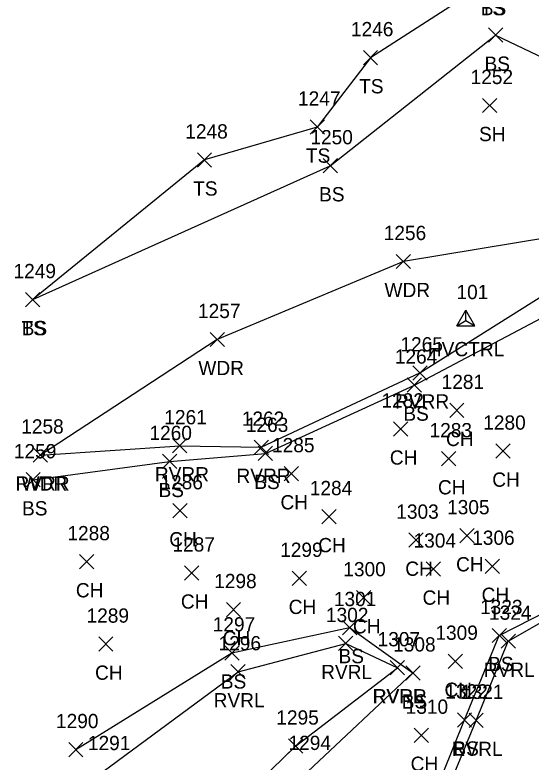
# Model space of a CAD drawing. Extents: x 1678553 to 1680768, y 787260 to 792325.
# Drawn here: x 1678583.5 to 1678655.8, y 787483.5 to 787588.2 of the extents above; entities that cross this region are included whole.
import ezdxf

# ---------------------------------------------------------------- set-up
doc = ezdxf.new("R2010")
doc.units = 0
for name, color, linetype in [('C_A', 7, 'Continuous'), ('C_I', 7, 'Continuous'), ('CPSM', 7, 'Continuous'), ('L_A', 7, 'Continuous'), ('L_I', 7, 'Continuous'), ('L_TIC', 7, 'Continuous'), ('LAWA', 7, 'Continuous'), ('LAWE', 7, 'Continuous'), ('LELB', 7, 'Continuous')]:
    doc.layers.add(name, color=color, linetype=linetype)

msp = doc.modelspace()

# ---------------------------------------------------------------- linework, layer by layer
at = {"layer": 'CPSM'}
for p, q in [((1678645.4, 787544.69), (1678646.65, 787546.85)), ((1678647.9, 787544.69), (1678646.65, 787546.85)), ((1678646.65, 787545.41), (1678646.65, 787546.85)), ((1678645.4, 787544.69), (1678646.65, 787545.41)), ((1678645.4, 787544.69), (1678647.9, 787544.69)), ((1678646.65, 787545.41), (1678646.65, 787545.41)), ((1678646.65, 787545.41), (1678647.9, 787544.69))]:
    msp.add_line(p, q, dxfattribs=at)
at = {"layer": 'L_TIC'}
for points in [[(1678649.83, 787584.41), (1678651.83, 787586.41)], [(1678651.83, 787584.41), (1678649.83, 787586.41)], [(1678632.3, 787581.25), (1678634.3, 787583.25)], [(1678634.3, 787581.25), (1678632.3, 787583.25)], [(1678649.01, 787574.55), (1678651.01, 787576.55)], [(1678651.01, 787574.55), (1678649.01, 787576.55)], [(1678624.84, 787571.53), (1678626.84, 787573.53)], [(1678626.84, 787571.53), (1678624.84, 787573.53)], [(1678609.05, 787566.92), (1678611.05, 787568.92)], [(1678611.05, 787566.92), (1678609.05, 787568.92)], [(1678626.66, 787566.11), (1678628.66, 787568.11)], [(1678628.66, 787566.11), (1678626.66, 787568.11)], [(1678636.9, 787552.69), (1678638.9, 787554.69)], [(1678638.9, 787552.69), (1678636.9, 787554.69)], [(1678585, 787547.35), (1678587, 787549.35)], [(1678587, 787547.35), (1678585, 787549.35)], [(1678585, 787547.35), (1678587, 787549.35)], [(1678587, 787547.35), (1678585, 787549.35)], [(1678610.83, 787541.76), (1678612.83, 787543.76)], [(1678612.83, 787541.76), (1678610.83, 787543.76)], [(1678639.23, 787537.08), (1678641.23, 787539.08)], [(1678641.23, 787537.08), (1678639.23, 787539.08)], [(1678638.45, 787535.37), (1678640.45, 787537.37)], [(1678640.45, 787535.37), (1678638.45, 787537.37)], [(1678644.39, 787531.82), (1678646.39, 787533.82)], [(1678646.39, 787531.82), (1678644.39, 787533.82)], [(1678636.52, 787529.22), (1678638.52, 787531.22)], [(1678638.52, 787529.22), (1678636.52, 787531.22)], [(1678605.59, 787526.87), (1678607.59, 787528.87)], [(1678607.59, 787526.87), (1678605.59, 787528.87)], [(1678617.01, 787526.66), (1678619.01, 787528.66)], [(1678619.01, 787526.66), (1678617.01, 787528.66)], [(1678650.87, 787526.12), (1678652.87, 787528.12)], [(1678652.87, 787526.12), (1678650.87, 787528.12)], [(1678586.07, 787525.57), (1678588.07, 787527.57)], [(1678588.07, 787525.57), (1678586.07, 787527.57)], [(1678586.07, 787525.57), (1678588.07, 787527.57)], [(1678588.07, 787525.57), (1678586.07, 787527.57)], [(1678617.58, 787525.8), (1678619.58, 787527.8)], [(1678619.58, 787525.8), (1678617.58, 787527.8)], [(1678643.26, 787525.05), (1678645.26, 787527.05)], [(1678645.26, 787525.05), (1678643.26, 787527.05)], [(1678604.17, 787524.67), (1678606.17, 787526.67)], [(1678606.17, 787524.67), (1678604.17, 787526.67)], [(1678621.21, 787522.95), (1678623.21, 787524.95)], [(1678623.21, 787522.95), (1678621.21, 787524.95)], [(1678585.05, 787522.1), (1678587.05, 787524.1)], [(1678587.05, 787522.1), (1678585.05, 787524.1)], [(1678605.63, 787517.76), (1678607.63, 787519.76)], [(1678607.63, 787517.76), (1678605.63, 787519.76)], [(1678626.49, 787516.94), (1678628.49, 787518.94)], [(1678628.49, 787516.94), (1678626.49, 787518.94)], [(1678638.68, 787513.64), (1678640.68, 787515.64)], [(1678640.68, 787513.64), (1678638.68, 787515.64)], [(1678645.8, 787514.26), (1678647.8, 787516.26)], [(1678647.8, 787514.26), (1678645.8, 787516.26)], [(1678592.54, 787510.62), (1678594.54, 787512.62)], [(1678594.54, 787510.62), (1678592.54, 787512.62)], [(1678641.1, 787509.59), (1678643.1, 787511.59)], [(1678643.1, 787509.59), (1678641.1, 787511.59)], [(1678649.37, 787509.98), (1678651.37, 787511.98)], [(1678651.37, 787509.98), (1678649.37, 787511.98)], [(1678607.26, 787509.04), (1678609.26, 787511.04)], [(1678609.26, 787509.04), (1678607.26, 787511.04)], [(1678622.35, 787508.29), (1678624.35, 787510.29)], [(1678624.35, 787508.29), (1678622.35, 787510.29)], [(1678631.35, 787505.57), (1678633.35, 787507.57)], [(1678633.35, 787505.57), (1678631.35, 787507.57)], [(1678613.11, 787503.91), (1678615.11, 787505.91)], [(1678615.11, 787503.91), (1678613.11, 787505.91)], [(1678629.37, 787501.39), (1678631.37, 787503.39)], [(1678631.37, 787501.39), (1678629.37, 787503.39)], [(1678650.34, 787500.28), (1678652.34, 787502.28)], [(1678652.34, 787500.28), (1678650.34, 787502.28)], [(1678595.23, 787499.07), (1678597.23, 787501.07)], [(1678597.23, 787499.07), (1678595.23, 787501.07)], [(1678628.83, 787499.16), (1678630.83, 787501.16)], [(1678630.83, 787499.16), (1678628.83, 787501.16)], [(1678651.59, 787499.48), (1678653.59, 787501.48)], [(1678653.59, 787499.48), (1678651.59, 787501.48)], [(1678612.89, 787497.84), (1678614.89, 787499.84)], [(1678614.89, 787497.84), (1678612.89, 787499.84)], [(1678644.17, 787496.67), (1678646.17, 787498.67)], [(1678646.17, 787496.67), (1678644.17, 787498.67)], [(1678636.07, 787495.76), (1678638.07, 787497.76)], [(1678638.07, 787495.76), (1678636.07, 787497.76)], [(1678636.07, 787495.76), (1678638.07, 787497.76)], [(1678638.07, 787495.76), (1678636.07, 787497.76)], [(1678613.76, 787495.2), (1678615.76, 787497.2)], [(1678615.76, 787495.2), (1678613.76, 787497.2)], [(1678638.24, 787495.03), (1678640.24, 787497.03)], [(1678640.24, 787495.03), (1678638.24, 787497.03)], [(1678638.24, 787495.03), (1678640.24, 787497.03)], [(1678640.24, 787495.03), (1678638.24, 787497.03)], [(1678645.47, 787488.44), (1678647.47, 787490.44)], [(1678647.47, 787488.44), (1678645.47, 787490.44)], [(1678647.1, 787488.38), (1678649.1, 787490.38)], [(1678649.1, 787488.38), (1678647.1, 787490.38)], [(1678639.43, 787486.3), (1678641.43, 787488.3)], [(1678641.43, 787486.3), (1678639.43, 787488.3)], [(1678591.03, 787484.29), (1678593.03, 787486.29)], [(1678593.03, 787484.29), (1678591.03, 787486.29)], [(1678621.8, 787484.79), (1678623.8, 787486.79)], [(1678623.8, 787484.79), (1678621.8, 787486.79)]]:
    msp.add_lwpolyline(points, dxfattribs=at)
at = {"layer": 'LAWA'}
msp.add_lwpolyline([(1678599.45, 787627.07), (1678621.63, 787630.48), (1678629.13, 787625.9), (1678659.68, 787623.11), (1678672.05, 787619.87), (1678670.06, 787610.94), (1678664.34, 787597.34), (1678663.82, 787591.2), (1678674.57, 787583.12), (1678678.14, 787577.87), (1678672.71, 787567.7), (1678658.82, 787557.15), (1678637.9, 787553.69), (1678611.83, 787542.76), (1678587.07, 787526.57)], dxfattribs=at)
at = {"layer": 'LAWE'}
for points in [[(1678587.07, 787526.57), (1678606.59, 787527.87), (1678618.01, 787527.66), (1678640.23, 787538.08), (1678659.07, 787549.93), (1678671.7, 787548.98), (1678686.58, 787560.22)], [(1678597.83, 787442.87), (1678614, 787449.69), (1678631.37, 787455.12), (1678641.6, 787473.63), (1678648.1, 787489.38), (1678652.59, 787500.48), (1678670.34, 787510.61)], [(1678595.85, 787482.21), (1678614.76, 787496.2), (1678629.83, 787500.16), (1678637.07, 787496.76)], [(1678597.76, 787461.45), (1678622.8, 787485.79), (1678637.07, 787496.76)]]:
    msp.add_lwpolyline(points, dxfattribs=at)
at = {"layer": 'LELB'}
for points in [[(1678650.31, 787593.2), (1678633.3, 787582.25), (1678625.84, 787572.53), (1678610.05, 787567.92), (1678586, 787548.35)], [(1678586, 787548.35), (1678627.66, 787567.11), (1678650.83, 787585.41), (1678664.45, 787578.91), (1678672.71, 787567.7)], [(1678586.05, 787523.1), (1678605.17, 787525.67), (1678618.58, 787526.8), (1678639.45, 787536.37), (1678659.67, 787547.06), (1678672.48, 787547.1), (1678689.05, 787558.27)], [(1678597.93, 787443.89), (1678613.14, 787451.8), (1678631.31, 787457.63), (1678640.51, 787474.59), (1678646.47, 787489.44), (1678651.34, 787501.28), (1678669.62, 787510.64)], [(1678592.03, 787485.29), (1678613.89, 787498.84), (1678630.37, 787502.39), (1678639.24, 787496.03)], [(1678598.77, 787460.97), (1678624.52, 787482.23), (1678639.24, 787496.03)]]:
    msp.add_lwpolyline(points, dxfattribs=at)

# ---------------------------------------------------------------- texts
at = {"layer": 'C_A'}
msp.add_text('HVCTRL', height=2, dxfattribs=at).set_placement((1678641.34, 787540.41))
at = {"layer": 'C_I'}
msp.add_text('101', height=2, dxfattribs=at).set_placement((1678645.34, 787548.41))
at = {"layer": 'L_A'}
for s, p in [('TS', (1678648.72, 787588.2)), ('BS', (1678648.75, 787588.2)), ('BS', (1678649.27, 787580.41)), ('TS', (1678631.71, 787577.25)), ('SH', (1678648.5, 787570.55)), ('TS', (1678624.25, 787567.53)), ('TS', (1678608.46, 787562.92)), ('BS', (1678626.1, 787562.11)), ('WDR', (1678635.26, 787548.69)), ('TS', (1678584.41, 787543.35)), ('BS', (1678584.44, 787543.35)), ('WDR', (1678609.19, 787537.76)), ('RVRR', (1678636.74, 787533.08)), ('BS', (1678637.9, 787531.37)), ('CH', (1678643.88, 787527.82)), ('CH', (1678636.01, 787525.22)), ('RVRR', (1678603.1, 787522.87)), ('RVRR', (1678614.53, 787522.66)), ('BS', (1678617.02, 787521.8)), ('CH', (1678650.35, 787522.12)), ('RVRR', (1678583.58, 787521.57)), ('WDR', (1678584.43, 787521.57)), ('BS', (1678603.61, 787520.67)), ('CH', (1678642.75, 787521.05)), ('CH', (1678620.69, 787518.95)), ('BS', (1678584.49, 787518.1)), ('CH', (1678605.11, 787513.76)), ('CH', (1678625.98, 787512.94)), ('CH', (1678645.29, 787510.26)), ('CH', (1678638.17, 787509.64)), ('CH', (1678592.03, 787506.62)), ('CH', (1678648.86, 787505.98)), ('CH', (1678606.74, 787505.04)), ('CH', (1678640.59, 787505.59)), ('CH', (1678621.84, 787504.29)), ('CH', (1678630.84, 787501.57)), ('CH', (1678612.6, 787499.91)), ('BS', (1678628.82, 787497.39)), ('RVRL', (1678649.16, 787495.48)), ('BS', (1678649.78, 787496.28)), ('CH', (1678594.72, 787495.07)), ('RVRL', (1678626.39, 787495.16)), ('BS', (1678612.33, 787493.84)), ('CH', (1678643.66, 787492.67)), ('RVRR', (1678633.59, 787491.76)), ('RVRL', (1678633.64, 787491.76)), ('RVRL', (1678611.33, 787491.2)), ('BS', (1678637.68, 787491.03)), ('BS', (1678637.68, 787491.03)), ('RVRL', (1678644.67, 787484.38)), ('BS', (1678644.91, 787484.44)), ('CH', (1678638.92, 787482.3))]:
    msp.add_text(s, height=2, dxfattribs=at).set_placement(p)
at = {"layer": 'L_I'}
for s, p in [('1246', (1678630.56, 787585.25)), ('1252', (1678647.32, 787578.55)), ('1247', (1678623.15, 787575.53)), ('1248', (1678607.36, 787570.92)), ('1250', (1678624.88, 787570.11)), ('1256', (1678635.15, 787556.69)), ('1249', (1678583.3, 787551.35)), ('1249', (1678583.3, 787551.35)), ('1257', (1678609.14, 787545.76)), ('1265', (1678637.49, 787541.08)), ('1264', (1678636.71, 787539.37)), ('1281', (1678643.26, 787535.82)), ('1282', (1678634.83, 787533.22)), ('1261', (1678604.42, 787530.87)), ('1262', (1678615.27, 787530.66)), ('1280', (1678649.09, 787530.12)), ('1258', (1678584.38, 787529.57)), ('1258', (1678584.38, 787529.57)), ('1263', (1678615.84, 787529.8)), ('1283', (1678641.57, 787529.05)), ('1260', (1678602.34, 787528.67)), ('1285', (1678619.51, 787526.95)), ('1259', (1678583.35, 787526.1)), ('1286', (1678603.88, 787521.76)), ('1284', (1678624.8, 787520.94)), ('1303', (1678636.91, 787517.64)), ('1305', (1678644.03, 787518.26)), ('1288', (1678590.85, 787514.62)), ('1304', (1678639.33, 787513.59)), ('1306', (1678647.54, 787513.98)), ('1287', (1678605.56, 787513.04)), ('1299', (1678620.65, 787512.29)), ('1300', (1678629.49, 787509.57)), ('1298', (1678611.41, 787507.91)), ('1301', (1678628.17, 787505.39)), ('1323', (1678648.65, 787504.28)), ('1289', (1678593.53, 787503.07)), ('1302', (1678627.06, 787503.16)), ('1324', (1678649.9, 787503.48)), ('1297', (1678611.2, 787501.84)), ('1309', (1678642.39, 787500.67)), ('1307', (1678634.3, 787499.76)), ('1307', (1678634.3, 787499.76)), ('1296', (1678612.02, 787499.2)), ('1308', (1678636.47, 787499.03)), ('1308', (1678636.47, 787499.03)), ('1322', (1678643.78, 787492.44)), ('1321', (1678645.97, 787492.38)), ('1310', (1678638.22, 787490.3)), ('1290', (1678589.25, 787488.29)), ('1295', (1678620.11, 787488.79)), ('1291', (1678593.72, 787485.21)), ('1294', (1678621.82, 787485.23))]:
    msp.add_text(s, height=2, dxfattribs=at).set_placement(p)

doc.saveas('drawing.dxf')
